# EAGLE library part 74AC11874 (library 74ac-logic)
Dual 4-bit D type edge triggered FLIP FLOP, 3-state
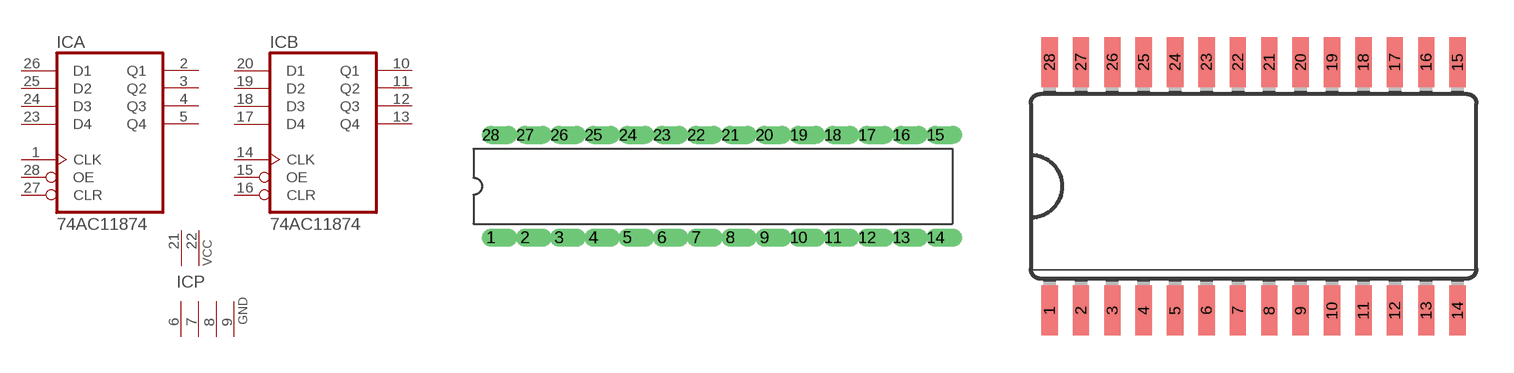
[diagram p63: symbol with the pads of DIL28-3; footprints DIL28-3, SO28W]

Designator prefix IC; gates A=7411874 B=7411874 P=2PWR4GND

## 74AC11874  [DIL28-3]
1  A:CLK  in
2  A:Q1  hiz
3  A:Q2  hiz
4  A:Q3  hiz
5  A:Q4  hiz
6  P:GND  pwr
7  P:GND  pwr
8  P:GND  pwr
9  P:GND  pwr
10  B:Q1  hiz
11  B:Q2  hiz
12  B:Q3  hiz
13  B:Q4  hiz
14  B:CLK  in
15  B:OE  in
16  B:CLR  in
17  B:D4  in
18  B:D3  in
19  B:D2  in
20  B:D1  in
21  P:VCC  pwr
22  P:VCC  pwr
23  A:D4  in
24  A:D3  in
25  A:D2  in
26  A:D1  in
27  A:CLR  in
28  A:OE  in

## 74AC11874D  [SO28W]
Pads as for DIL28-3

## Footprint DIL28-3 (pad centres in mm)
Dual In Line 0.3 inch
drill 0.813 offset: 1 -16.51,-3.81; 2 -13.97,-3.81; 3 -11.43,-3.81; 4 -8.89,-3.81; 5 -6.35,-3.81; 6 -3.81,-3.81; 7 -1.27,-3.81; 8 1.27,-3.81; 9 3.81,-3.81; 10 6.35,-3.81; 11 8.89,-3.81; 12 11.43,-3.81; 13 13.97,-3.81; 14 16.51,-3.81; 15 16.51,3.81; 16 13.97,3.81; 17 11.43,3.81; 18 8.89,3.81; 19 6.35,3.81; 20 3.81,3.81; 21 1.27,3.81; 22 -1.27,3.81; 23 -3.81,3.81; 24 -6.35,3.81; 25 -8.89,3.81; 26 -11.43,3.81; 27 -13.97,3.81; 28 -16.51,3.81

## Footprint SO28W (pad centres in mm)
Wide Small Outline package 300 mil
smd 0.66 x 2.032: 1 -8.255,-5.029; 2 -6.985,-5.029; 3 -5.715,-5.029; 4 -4.445,-5.029; 5 -3.175,-5.029; 6 -1.905,-5.029; 7 -0.635,-5.029; 8 0.635,-5.029; 9 1.905,-5.029; 10 3.175,-5.029; 11 4.445,-5.029; 12 5.715,-5.029; 13 6.985,-5.029; 14 8.255,-5.029; 15 8.255,5.029; 16 6.985,5.029; 17 5.715,5.029; 18 4.445,5.029; 19 3.175,5.029; 20 1.905,5.029; 21 0.635,5.029; 22 -0.635,5.029; 23 -1.905,5.029; 24 -3.175,5.029; 25 -4.445,5.029; 26 -5.715,5.029; 27 -6.985,5.029; 28 -8.255,5.029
